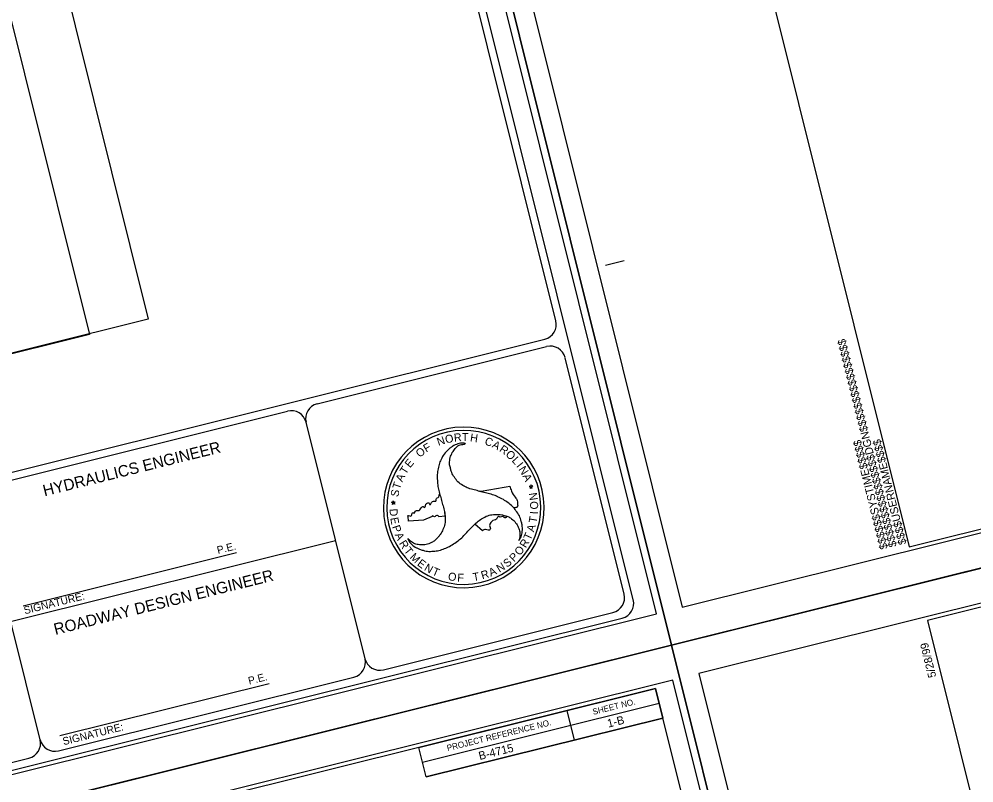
# Model space of a CAD drawing. Extents: x 1030323 to 1034123, y 654802 to 657751.
# Drawn here: x 1031795 to 1032422, y 656186 to 656687 of the extents above; entities that cross this region are included whole.
import ezdxf

# ---------------------------------------------------------------- set-up
doc = ezdxf.new("R2010")
doc.units = 0
for name, color, linetype in [('Sheet Clip Boundary CELL', 7, 'Continuous'), ('Sheet Cutting Line CELL', 7, 'Continuous'), ('Sheet Data Field CELL', 7, 'Continuous'), ('Sheet Plot Border Inside CELL', 7, 'Continuous'), ('Sheet Plot Border Outside CELL', 7, 'Continuous'), ('Sheet Summary CELL', 7, 'Continuous'), ('Sheet Symbology CELL', 7, 'Continuous'), ('Sheet Title CELL', 7, 'Continuous')]:
    doc.layers.add(name, color=color, linetype=linetype)

msp = doc.modelspace()

# ---------------------------------------------------------------- linework, layer by layer
at = {"layer": 'Sheet Clip Boundary CELL'}
msp.add_lwpolyline([(1031088.75, 656293.37), (1030994.11, 656269.56), (1030843.5, 656511.74), (1030969.21, 656567.19), (1030968.58, 656775.34), (1031272.57, 656874.34), (1031522.82, 656933.1), (1031562.8, 656947.62), (1031759.53, 656972.55), (1031879.7, 656490.58)], close=True, dxfattribs=at)
at = {"layer": 'Sheet Cutting Line CELL'}
for p, q in [((1031956.96, 657343.76), (1032223.08, 656276.43)), ((1033857.05, 656683.84), (1032223.08, 656276.44)), ((1032223.08, 656276.43), (1033857.06, 656683.83)), ((1030589.1, 655869.05), (1032223.08, 656276.44)), ((1032223.08, 656276.44), (1030589.1, 655869.05)), ((1032223.08, 656276.44), (1032489.19, 655209.12))]:
    msp.add_line(p, q, dxfattribs=at)
at = {"layer": 'Sheet Plot Border Inside CELL'}
for points in [[(1033592.01, 657728.28), (1031975.01, 657325.12), (1032230.26, 656301.36), (1033847.26, 656704.52)], [(1030596.28, 655893.96), (1032213.28, 656297.13), (1031958.03, 657320.89), (1030341.03, 656917.72)], [(1033858.12, 656660.97), (1032241.12, 656257.81), (1032496.37, 655234.05), (1034113.37, 655637.21)], [(1030862.39, 654826.65), (1032479.39, 655229.81), (1032224.14, 656253.57), (1030607.14, 655850.41)]]:
    msp.add_lwpolyline(points, close=True, dxfattribs=at)
at = {"layer": 'Sheet Plot Border Outside CELL'}
for points in [[(1033590.94, 657751.15), (1031956.96, 657343.76), (1032223.08, 656276.43), (1033857.06, 656683.83)], [(1031956.96, 657343.76), (1030322.99, 656936.36), (1030589.1, 655869.05), (1032223.08, 656276.44)], [(1033857.05, 656683.84), (1032223.08, 656276.44), (1032489.19, 655209.12), (1034123.17, 655616.52)], [(1030855.21, 654801.72), (1032489.19, 655209.12), (1032223.08, 656276.44), (1030589.1, 655869.05)]]:
    msp.add_lwpolyline(points, close=True, dxfattribs=at)
at = {"layer": 'Sheet Summary CELL'}
for p, q in [((1032179.94, 656525.91), (1032192.07, 656528.93)), ((1032379.07, 656341.09), (1032379.07, 656341.09)), ((1032379.07, 656341.09), (1032379.07, 656341.09)), ((1032379.07, 656341.09), (1032379.07, 656341.09)), ((1032379.07, 656341.09), (1032379.07, 656341.09)), ((1032379.07, 656341.09), (1032379.07, 656341.09)), ((1032379.07, 656341.09), (1032379.07, 656341.09)), ((1032391.16, 656292.59), (1032400.95, 656253.34))]:
    msp.add_line(p, q, dxfattribs=at)
for points in [[(1033580.5, 657722.78), (1032125.05, 657359.9), (1032379.07, 656341.09), (1033834.51, 656703.97)], [(1033846.61, 656655.47), (1032391.16, 656292.59), (1032645.18, 655273.78), (1034100.62, 655636.66)]]:
    msp.add_lwpolyline(points, close=True, dxfattribs=at)
at = {"layer": 'Sheet Symbology CELL'}
for p, q in [((1032059.77, 656199.62), (1032215.06, 656238.34)), ((1032154.42, 656233.52), (1032159.26, 656214.12)), ((1032062.19, 656189.92), (1032217.48, 656228.63))]:
    msp.add_line(p, q, dxfattribs=at)
for points in [[(1032212.63, 656248.07), (1030757.19, 655885.19), (1031010.96, 654867.37), (1032466.4, 655230.25)], [(1032057.34, 656209.36), (1032212.63, 656248.07), (1032217.48, 656228.63), (1032062.19, 656189.92)]]:
    msp.add_lwpolyline(points, close=True, dxfattribs=at)
at = {"layer": 'Sheet Title CELL'}
for p, q in [((1030762.19, 656133.79), (1032140.01, 656477.32)), ((1031990.6, 656434.91), (1032141.22, 656472.47)), ((1031777.36, 656381.74), (1031971.2, 656430.07)), ((1032022.03, 656267.54), (1031983.32, 656422.79)), ((1032087.75, 656409.04), (1032087.67, 656408.92)), ((1032087.75, 656409.04), (1032087.67, 656408.92)), ((1032130.83, 656381.69), (1032130.65, 656380.82)), ((1032131.24, 656380.88), (1032130.83, 656381.69)), ((1032096.98, 656377.5), (1032096.98, 656377.5)), ((1032130.65, 656380.82), (1032129.75, 656380.72)), ((1032129.75, 656380.72), (1032130.55, 656380.27)), ((1032130.55, 656380.27), (1032130.39, 656379.37)), ((1032130.39, 656379.37), (1032131.03, 656379.98)), ((1032131.03, 656379.98), (1032131.82, 656379.53)), ((1032132.12, 656381.02), (1032131.24, 656380.88)), ((1032131.45, 656380.37), (1032132.12, 656381.02)), ((1032131.82, 656379.53), (1032131.45, 656380.37)), ((1031808.79, 656214.36), (1031770.08, 656369.61)), ((1032039.52, 656370.26), (1032040.44, 656370.37)), ((1032040.31, 656369.8), (1032039.52, 656370.26)), ((1032040.15, 656368.9), (1032040.31, 656369.8)), ((1032040.79, 656369.53), (1032040.15, 656368.9)), ((1032040.44, 656370.37), (1032040.59, 656371.23)), ((1032040.59, 656371.23), (1032041, 656370.43)), ((1032041.59, 656369.07), (1032040.79, 656369.53)), ((1032041, 656370.43), (1032041.9, 656370.53)), ((1032041.9, 656370.53), (1032041.21, 656369.9)), ((1032041.21, 656369.9), (1032041.59, 656369.07)), ((1032139.25, 656372.82), (1032139.25, 656372.82)), ((1032050.51, 656357.84), (1032050.27, 656361)), ((1032060.49, 656358.58), (1032050.51, 656357.84)), ((1032066, 656360.9), (1032060.49, 656358.58)), ((1032074.6, 656361.16), (1032070.45, 656360.74)), ((1032099.14, 656351.61), (1032094.21, 656355.88)), ((1032094.21, 656355.88), (1032094.21, 656355.88)), ((1031788.55, 656291.8), (1032002.67, 656345.19)), ((1031797.68, 656302.31), (1031937.64, 656337.21)), ((1031821.77, 656217.05), (1031959.07, 656251.27))]:
    msp.add_line(p, q, dxfattribs=at)
for points in [[(1032198.11, 656306.29), (1031948.94, 657305.68)], [(1032147.3, 656489.43), (1031945.29, 657299.64)], [(1031755.78, 656823), (1031841.22, 656480.34), (1031050.26, 656283.14), (1030953.9, 656669.65)], [(1032192.05, 656309.93), (1032153.34, 656465.18)], [(1030754.79, 655936.11), (1032190.83, 656294.16)], [(1032034.15, 656260.26), (1032184.77, 656297.81)], [(1031820.91, 656207.09), (1032014.75, 656255.42)], [(1031524.97, 656133.31), (1031801.5, 656202.24)]]:
    msp.add_lwpolyline(points, dxfattribs=at)
for centre, radius, start, end in [((1032137.59, 656487.06), 10, 284, 14), ((1032143.63, 656462.81), 10, 14, 104), ((1031993.02, 656425.21), 10, 104, 194), ((1031973.62, 656420.37), 10, 14, 104), ((1032086.87, 656366.92), 52.72, 6.42113, 186.42113), ((1032086.87, 656366.92), 50.52, 6.42113, 186.42113), ((1032060.51, 656653.04), 277.94, 272.09962, 272.19922), ((1032060.51, 656653.04), 277.94, 277.53868, 281.74469), ((1032086.87, 656366.92), 52.72, 186.42113, 6.42113), ((1032086.87, 656366.92), 50.52, 186.42113, 6.42113), ((1032182.34, 656307.56), 10, 284, 14), ((1032188.4, 656303.92), 10, 284, 14), ((1032012.32, 656265.18), 10, 284, 14), ((1032031.72, 656270.02), 10, 194, 284), ((1031799.08, 656212), 10, 284, 14), ((1031818.48, 656216.84), 10, 194, 284)]:
    msp.add_arc(centre, radius, start, end, dxfattribs=at)
for points in [[(1032087.67, 656408.92), (1032086.46, 656409.1), (1032083, 656408.57), (1032079.58, 656407.04), (1032079.29, 656406.83), (1032077.63, 656405.7), (1032075.91, 656404.09), (1032073.37, 656401.09), (1032071.56, 656397.53), (1032070.85, 656396.02), (1032070.41, 656394.21), (1032069.66, 656390.39), (1032069.46, 656386.75), (1032069.7, 656382.54), (1032070.17, 656378.89), (1032071.2, 656375.21), (1032072.28, 656371.51), (1032073.23, 656367.91), (1032074.17, 656364.19), (1032074.61, 656360.45), (1032074.63, 656360.13), (1032074.41, 656356.06), (1032073.19, 656352.39), (1032071.44, 656349.22), (1032070.36, 656347.73), (1032068.76, 656346.16), (1032067.86, 656345.26), (1032065.62, 656343.78), (1032062.12, 656342.54), (1032058.59, 656342.35), (1032055.4, 656342.79), (1032052.47, 656344.24), (1032050.03, 656346.51)], [(1032122.93, 656345.14), (1032123.65, 656346.07), (1032124.95, 656349.34), (1032125.33, 656353.06), (1032125.33, 656353.43), (1032125.14, 656355.43), (1032124.61, 656357.75), (1032123.32, 656361.45), (1032121.1, 656364.76), (1032120.18, 656366.15), (1032118.8, 656367.46), (1032115.87, 656370), (1032112.84, 656372), (1032109.07, 656373.88), (1032105.66, 656375.27), (1032101.95, 656376.27), (1032098.23, 656377.17), (1032094.66, 656378.14), (1032090.91, 656379.19), (1032087.49, 656380.68), (1032087.2, 656380.85), (1032083.74, 656383.07), (1032081.18, 656385.97), (1032079.3, 656389.05), (1032078.61, 656390.72), (1032078.05, 656392.9), (1032077.67, 656394.15), (1032077.56, 656396.81), (1032078.21, 656400.48), (1032079.8, 656403.6), (1032081.79, 656406.14), (1032084.53, 656407.96), (1032087.67, 656408.92), (1032087.75, 656409.04)], [(1032050.27, 656361), (1032050.13, 656361.28), (1032050.61, 656361.68), (1032052.16, 656361.25), (1032052.83, 656361.97), (1032052.73, 656362.6), (1032053.25, 656363.3), (1032054.28, 656363.21), (1032055.06, 656364.48), (1032055.88, 656364.78), (1032057.65, 656364.98), (1032059.51, 656367.32), (1032060.38, 656367.55), (1032060.66, 656367.01), (1032061.22, 656366.97), (1032061.92, 656368.81), (1032062.13, 656369.08), (1032063.7, 656369.92), (1032064.17, 656369.66), (1032064.38, 656368.89), (1032064.63, 656368.77), (1032065.13, 656369.21), (1032065.75, 656370.23), (1032067.03, 656371.08), (1032068.58, 656371.07), (1032068.71, 656372.35), (1032070.37, 656373.77), (1032070.66, 656374.54), (1032070.67, 656375.29)], [(1032071.17, 656375.3), (1032071.2, 656375.21), (1032072.28, 656371.51), (1032073.23, 656367.91), (1032074.17, 656364.19), (1032074.59, 656361.16)], [(1032119.73, 656366.66), (1032118.8, 656367.46), (1032115.87, 656370), (1032112.84, 656372), (1032109.07, 656373.88), (1032105.66, 656375.27), (1032101.95, 656376.27), (1032098.23, 656377.17), (1032096.98, 656377.5)], [(1032117.08, 656380.91), (1032118.22, 656377.5), (1032120.52, 656373.59), (1032121.95, 656371.47), (1032122.14, 656369.53), (1032121.95, 656367.17), (1032119.74, 656366.68)], [(1032050.03, 656346.51), (1032050.53, 656345.37), (1032052.71, 656342.63), (1032055.73, 656340.42), (1032056.04, 656340.3), (1032057.89, 656339.39), (1032060.13, 656338.73), (1032064.02, 656338), (1032067.95, 656338.26), (1032069.62, 656338.37), (1032071.49, 656338.92), (1032075.1, 656340.18), (1032078.34, 656341.79), (1032081.88, 656344.12), (1032084.78, 656346.35), (1032087.49, 656349.09), (1032090.13, 656351.89), (1032092.79, 656354.5), (1032095.56, 656357.15), (1032098.56, 656359.42), (1032098.9, 656359.6), (1032102.53, 656361.46), (1032106.28, 656362.23), (1032109.85, 656362.31), (1032111.74, 656362.13), (1032113.85, 656361.47), (1032115.15, 656361.2), (1032117.51, 656359.97), (1032120.31, 656357.56), (1032122.24, 656354.64), (1032123.46, 656351.61), (1032123.67, 656348.35), (1032122.93, 656345.14)], [(1032094.21, 656355.88), (1032095.56, 656357.15), (1032098.56, 656359.42), (1032098.9, 656359.6), (1032102.53, 656361.46), (1032106.28, 656362.23), (1032109.85, 656362.31), (1032111.74, 656362.13), (1032113.85, 656361.47), (1032115.06, 656361.2)], [(1032070.45, 656360.74), (1032069.96, 656361.46), (1032069.13, 656361.6), (1032068.11, 656360.9), (1032067.28, 656360.86), (1032066.31, 656361.41), (1032066, 656360.9)], [(1032115.04, 656361.18), (1032114.67, 656360.21), (1032113.88, 656360.06), (1032112.37, 656361.01), (1032110.72, 656360.48), (1032109.89, 656360.84), (1032109.38, 656360.8), (1032108.33, 656359.12), (1032106.69, 656358.56), (1032104.2, 656356.25), (1032103.77, 656355.03), (1032104.26, 656352.53), (1032103.64, 656351.96), (1032102.82, 656351.99), (1032101.07, 656352.46), (1032099.14, 656351.61)]]:
    msp.add_spline(points, degree=3, dxfattribs=at)

# ---------------------------------------------------------------- texts
at = {"layer": 'Sheet Data Field CELL'}
for s, p in [('1-B', (1032181.77, 656222.32)), ('B-4715', (1032097.33, 656201.02))]:
    msp.add_text(s, height=5.4, rotation=14, dxfattribs=at).set_placement(p)
at = {"layer": 'Sheet Summary CELL'}
for s, p in [('$$$$$$$$$$$$$$$$DGN$$$$$$$$$$$$$$$$', (1032371.08, 656341.53)), ('$$$$$$SYSTIME$$$$$', (1032365.21, 656340.07)), ('$$$$USERNAME$$$$', (1032377.45, 656343.14)), ('5/28/99', (1032396.98, 656255.8))]:
    msp.add_text(s, height=5.25, rotation=104, dxfattribs=at).set_placement(p)
at = {"layer": 'Sheet Symbology CELL'}
for s, p in [('SHEET NO.', (1032171.87, 656230.66)), ('PROJECT REFERENCE NO.', (1032076.26, 656206.9))]:
    msp.add_text(s, height=4, rotation=14, dxfattribs=at).set_placement(p)
at = {"layer": 'Sheet Title CELL'}
for s, height, rotation, p in [('N', 5.26, 19.40491, (1032070.29, 656407.19)), ('O', 5.27, 11.9068, (1032075.15, 656408.87)), ('R', 5.26, 5.29687, (1032080.59, 656410.01)), ('T', 5.27, 358.64724, (1032085.6, 656410.48)), ('H', 5.25, 351.56252, (1032090.74, 656410.32)), ('C', 5.24, 339.22017, (1032100.07, 656408.45)), (' HYDRAULICS ENGINEER', 7.5, 14, (1031808.97, 656373.47)), ('F', 5.27, 31.49185, (1032062.24, 656402.84)), ('A', 5.25, 331.72314, (1032104.97, 656406.56)), ('R', 5.25, 325.35919, (1032109.72, 656404.01)), ('O', 5.26, 38.63869, (1032057.88, 656399.39)), ('O', 5.27, 318.23959, (1032113.85, 656401.14)), ('L', 5.24, 312.00591, (1032118.03, 656397.42)), ('T', 5.24, 57.6937, (1032048.85, 656388.15)), ('E', 5.24, 50.57807, (1032051.61, 656392.49)), ('I', 5.26, 308.01657, (1032120.99, 656393.98)), ('N', 5.25, 302.31647, (1032122.54, 656391.93)), ('A', 5.27, 64.74892, (1032046.52, 656383.24)), ('A', 5.26, 294.88449, (1032125.27, 656387.56)), ('T', 5.27, 71.80123, (1032044.85, 656378.38)), ('S', 5.25, 78.17738, (1032043.81, 656373.48)), ('N', 5.26, 98.62926, (1032135.5, 656371.96)), ('O', 5.24, 91.38125, (1032135.71, 656365.62)), ('D', 5.26, 274.27413, (1032038.06, 656365.92)), ('I', 5.27, 86.24562, (1032135.52, 656362.25)), ('E', 5.23, 280.56202, (1032038.57, 656359.9)), ('T', 5.25, 80.59571, (1032134.58, 656356.39)), ('P', 5.26, 288.09441, (1032039.71, 656354.31)), ('T', 5.24, 65.42425, (1032130.49, 656344.93)), ('A', 5.27, 73.51129, (1032132.88, 656350.39)), ('P.E.', 5, 14, (1031925.54, 656336.3)), ('A', 5.25, 294.68699, (1032041.46, 656348.97)), ('R', 5.26, 301.75562, (1032044.12, 656343.34)), ('R', 5.27, 59.32446, (1032127.58, 656339.89)), ('T', 5.25, 308.40616, (1032047.22, 656338.44)), ('O', 5.27, 52.13535, (1032123.72, 656334.85)), ('M', 5.24, 315.6412, (1032051, 656333.82)), ('E', 5.24, 323.10797, (1032055.86, 656329.22)), ('S', 5.23, 38.25151, (1032115.25, 656327.18)), ('P', 5.25, 45.44336, (1032119.8, 656330.81)), ('ROADWAY DESIGN ENGINEER', 7.4994, 14, (1031818.82, 656283.15)), ('N', 5.27, 330.07951, (1032060.43, 656325.87)), ('T', 5.25, 336.92151, (1032065.6, 656322.96)), ('R', 5.26, 17.25628, (1032099.06, 656319.6)), ('A', 5.24, 24.00941, (1032104.58, 656321.41)), ('N', 5.24, 31.04104, (1032110.22, 656324.02)), ('O', 5.25, 350.2252, (1032076.19, 656319.26)), ('F', 5.25, 357.39043, (1032082.47, 656318.27)), ('T', 5.24, 10.29966, (1032093.21, 656318.47)), ('SIGNATURE:', 5, 14, (1031798.79, 656296.72)), ('P.E.', 5, 14, (1031946.02, 656250.5)), ('SIGNATURE:', 5, 14, (1031824.27, 656210.76))]:
    msp.add_text(s, height=height, rotation=rotation, dxfattribs=at).set_placement(p)

doc.saveas('drawing.dxf')
